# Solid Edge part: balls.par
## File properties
Title: Bearing
Author: Abhinav Rai
Template: Normal.par
Last saved by: TIET
Revision: 10
Application: Solid Edge
Accuracy: 0.99
Material: aluminum
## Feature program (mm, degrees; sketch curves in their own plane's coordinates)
sketch for "unnamed RevolvedProtrusion 1" plane through (0, 0, 0) normal (0, -1, 0) x-axis (1, 0, 0)
  arc centre (0, 0) radius 6.604 from (0, 6.604) to (0, -6.604) cw
  line (0, 6.604) -> (0, -6.604)
revolve "unnamed RevolvedProtrusion 1" add full turn 360 deg
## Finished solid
Body 1: solid body, 1 face, 0 edges, 0 vertices.
  Faces by surface: sphere 1
Spherical faces by radius (mm): R6.604 x1
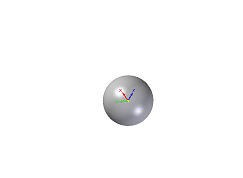
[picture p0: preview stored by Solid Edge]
